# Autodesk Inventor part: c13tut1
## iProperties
Created: 2002-04
Part Number: c13tut1
Document SubType Name: Modeling
Control State: 0
Master: False
Checked Out: False
Shininess: 64.0
Angle Display Precision: 2
Document Length Units: 11269
Document Angle Units: 11279
Document Time Units: 11290
Document Mass Units: 11283
Document Length Units Precision: 3
Document Angle Units Precision: 2
Compacted: True
Density: 0.0
Volumn: 0.0
Area: 0.0
PropertySet Name: Model Information
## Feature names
1. Extrusion1
